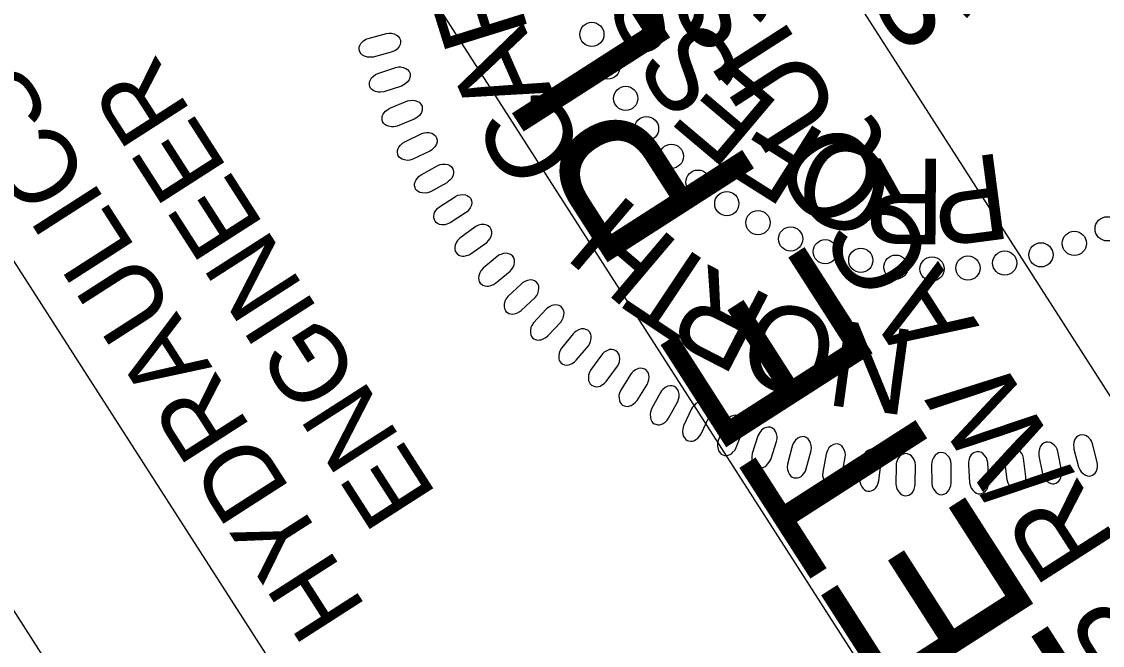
# Model space of a CAD drawing. Extents: x 476646 to 478477, y 498681 to 500689.
# Drawn here: x 476726.9 to 476798.5, y 500059.2 to 500100.5 of the extents above; entities that cross this region are included whole.
import ezdxf

# ---------------------------------------------------------------- set-up
doc = ezdxf.new("R2010")
doc.units = 0
for name, color, linetype in [('Sheet PE Seal Cell', 7, 'Continuous'), ('Sheet Plan CELL', 7, 'Continuous'), ('Sheet Sticker Incomplete CELL', 7, 'Continuous')]:
    doc.layers.add(name, color=color, linetype=linetype)

msp = doc.modelspace()

# ---------------------------------------------------------------- linework, layer by layer
at = {"layer": 'Sheet PE Seal Cell'}
for points in [[(476751.41, 500098.486), (476750.223, 500098.175), (476750.001, 500098.156), (476749.853, 500098.171), (476749.66, 500098.237), (476749.53, 500098.303), (476749.424, 500098.391), (476749.359, 500098.482), (476749.312, 500098.586), (476749.303, 500098.699), (476749.302, 500098.823), (476749.333, 500098.94), (476749.403, 500099.065), (476749.465, 500099.144), (476749.592, 500099.247), (476749.751, 500099.35), (476749.9, 500099.412), (476751.113, 500099.737), (476751.283, 500099.759), (476751.43, 500099.75), (476751.607, 500099.704), (476751.77, 500099.631), (476751.872, 500099.557), (476751.97, 500099.42), (476752.026, 500099.28), (476752.026, 500099.126), (476752.004, 500099.012), (476751.94, 500098.864), (476751.806, 500098.706), (476751.65, 500098.595), (476751.531, 500098.533)], [(476752.101, 500096.256), (476750.937, 500095.872), (476750.717, 500095.839), (476750.567, 500095.845), (476750.371, 500095.898), (476750.237, 500095.955), (476750.126, 500096.037), (476750.055, 500096.124), (476750, 500096.224), (476749.984, 500096.337), (476749.976, 500096.46), (476750, 500096.578), (476750.062, 500096.708), (476750.118, 500096.79), (476750.24, 500096.901), (476750.391, 500097.014), (476750.536, 500097.086), (476751.727, 500097.487), (476751.895, 500097.518), (476752.042, 500097.519), (476752.221, 500097.484), (476752.389, 500097.421), (476752.495, 500097.354), (476752.601, 500097.224), (476752.667, 500097.088), (476752.675, 500096.934), (476752.661, 500096.819), (476752.606, 500096.667), (476752.483, 500096.5), (476752.333, 500096.38), (476752.22, 500096.311)], [(476752.947, 500094.06), (476751.809, 500093.603), (476751.591, 500093.556), (476751.443, 500093.553), (476751.243, 500093.594), (476751.106, 500093.643), (476750.99, 500093.717), (476750.914, 500093.8), (476750.853, 500093.896), (476750.83, 500094.008), (476750.813, 500094.13), (476750.83, 500094.25), (476750.884, 500094.384), (476750.935, 500094.469), (476751.049, 500094.587), (476751.193, 500094.71), (476751.333, 500094.79), (476752.497, 500095.265), (476752.662, 500095.306), (476752.808, 500095.317), (476752.99, 500095.293), (476753.161, 500095.241), (476753.272, 500095.181), (476753.385, 500095.057), (476753.46, 500094.926), (476753.478, 500094.773), (476753.471, 500094.657), (476753.426, 500094.502), (476753.313, 500094.328), (476753.172, 500094.198), (476753.062, 500094.122)], [(476753.969, 500091.936), (476752.862, 500091.409), (476752.647, 500091.348), (476752.499, 500091.336), (476752.298, 500091.364), (476752.157, 500091.405), (476752.037, 500091.472), (476751.956, 500091.549), (476751.89, 500091.641), (476751.86, 500091.752), (476751.835, 500091.872), (476751.844, 500091.992), (476751.889, 500092.13), (476751.935, 500092.218), (476752.041, 500092.344), (476752.178, 500092.474), (476752.312, 500092.563), (476753.444, 500093.11), (476753.607, 500093.162), (476753.751, 500093.182), (476753.934, 500093.17), (476754.109, 500093.129), (476754.222, 500093.075), (476754.344, 500092.959), (476754.426, 500092.833), (476754.454, 500092.681), (476754.455, 500092.565), (476754.419, 500092.407), (476754.318, 500092.226), (476754.184, 500092.088), (476754.08, 500092.005)], [(476755.098, 500089.854), (476754.025, 500089.257), (476753.816, 500089.183), (476753.668, 500089.161), (476753.465, 500089.177), (476753.322, 500089.209), (476753.198, 500089.268), (476753.113, 500089.34), (476753.04, 500089.429), (476753.004, 500089.536), (476752.972, 500089.655), (476752.973, 500089.776), (476753.009, 500089.916), (476753.05, 500090.007), (476753.148, 500090.138), (476753.276, 500090.278), (476753.404, 500090.375), (476754.499, 500090.992), (476754.658, 500091.055), (476754.802, 500091.083), (476754.985, 500091.082), (476755.161, 500091.052), (476755.279, 500091.006), (476755.407, 500090.898), (476755.498, 500090.777), (476755.535, 500090.627), (476755.542, 500090.511), (476755.517, 500090.351), (476755.427, 500090.165), (476755.303, 500090.019), (476755.203, 500089.929)], [(476756.349, 500087.853), (476755.317, 500087.191), (476755.112, 500087.105), (476754.965, 500087.073), (476754.763, 500087.076), (476754.618, 500087.099), (476754.49, 500087.15), (476754.4, 500087.216), (476754.323, 500087.3), (476754.279, 500087.405), (476754.239, 500087.522), (476754.234, 500087.642), (476754.261, 500087.784), (476754.296, 500087.878), (476754.386, 500088.015), (476754.504, 500088.163), (476754.627, 500088.268), (476755.68, 500088.952), (476755.835, 500089.025), (476755.977, 500089.062), (476756.16, 500089.073), (476756.338, 500089.054), (476756.457, 500089.015), (476756.593, 500088.915), (476756.69, 500088.8), (476756.737, 500088.653), (476756.752, 500088.538), (476756.737, 500088.377), (476756.658, 500088.185), (476756.543, 500088.031), (476756.45, 500087.936)], [(476756.959, 500086.92), (476755.97, 500086.194), (476755.815, 500086.034), (476755.734, 500085.91), (476755.663, 500085.718), (476755.632, 500085.575), (476755.634, 500085.438), (476755.664, 500085.33), (476755.714, 500085.227), (476755.797, 500085.149), (476755.891, 500085.07), (476756.001, 500085.021), (476756.144, 500084.996), (476756.243, 500084.995), (476756.404, 500085.029), (476756.584, 500085.087), (476756.726, 500085.163), (476757.744, 500085.901), (476757.867, 500086.019), (476757.953, 500086.138), (476758.029, 500086.304), (476758.075, 500086.478), (476758.082, 500086.603), (476758.037, 500086.765), (476757.965, 500086.897), (476757.844, 500086.994), (476757.742, 500087.049), (476757.586, 500087.092), (476757.379, 500087.089), (476757.194, 500087.036), (476757.072, 500086.984)], [(476758.446, 500084.977), (476757.505, 500084.19), (476757.36, 500084.021), (476757.287, 500083.892), (476757.228, 500083.697), (476757.206, 500083.552), (476757.217, 500083.415), (476757.254, 500083.309), (476757.31, 500083.21), (476757.397, 500083.137), (476757.497, 500083.064), (476757.61, 500083.022), (476757.753, 500083.005), (476757.853, 500083.011), (476758.011, 500083.055), (476758.187, 500083.124), (476758.324, 500083.209), (476759.293, 500084.009), (476759.409, 500084.135), (476759.488, 500084.259), (476759.553, 500084.43), (476759.588, 500084.605), (476759.586, 500084.731), (476759.532, 500084.89), (476759.452, 500085.018), (476759.325, 500085.107), (476759.22, 500085.155), (476759.062, 500085.189), (476758.855, 500085.172), (476758.674, 500085.108), (476758.556, 500085.048)], [(476760.042, 500083.171), (476759.152, 500082.328), (476759.018, 500082.15), (476758.952, 500082.016), (476758.907, 500081.817), (476758.894, 500081.672), (476758.913, 500081.535), (476758.956, 500081.432), (476759.019, 500081.336), (476759.11, 500081.269), (476759.214, 500081.203), (476759.329, 500081.168), (476759.475, 500081.16), (476759.573, 500081.172), (476759.728, 500081.227), (476759.899, 500081.306), (476760.031, 500081.4), (476760.948, 500082.259), (476761.056, 500082.392), (476761.126, 500082.52), (476761.18, 500082.695), (476761.204, 500082.873), (476761.195, 500082.998), (476761.131, 500083.153), (476761.042, 500083.275), (476760.911, 500083.356), (476760.802, 500083.398), (476760.643, 500083.422), (476760.437, 500083.392), (476760.261, 500083.317), (476760.146, 500083.249)], [(476761.684, 500081.486), (476760.848, 500080.588), (476760.726, 500080.402), (476760.669, 500080.264), (476760.636, 500080.063), (476760.633, 500079.917), (476760.66, 500079.782), (476760.709, 500079.681), (476760.778, 500079.59), (476760.874, 500079.528), (476760.982, 500079.469), (476761.099, 500079.442), (476761.244, 500079.444), (476761.342, 500079.461), (476761.493, 500079.525), (476761.659, 500079.615), (476761.784, 500079.717), (476762.645, 500080.632), (476762.745, 500080.771), (476762.807, 500080.904), (476762.85, 500081.082), (476762.863, 500081.261), (476762.846, 500081.385), (476762.772, 500081.536), (476762.676, 500081.652), (476762.54, 500081.725), (476762.429, 500081.76), (476762.268, 500081.773), (476762.065, 500081.731), (476761.893, 500081.645), (476761.784, 500081.571)], [(476763.467, 500079.857), (476762.689, 500078.908), (476762.579, 500078.715), (476762.531, 500078.574), (476762.51, 500078.372), (476762.515, 500078.225), (476762.551, 500078.092), (476762.607, 500077.995), (476762.681, 500077.909), (476762.781, 500077.852), (476762.892, 500077.801), (476763.01, 500077.78), (476763.155, 500077.791), (476763.252, 500077.815), (476763.399, 500077.888), (476763.559, 500077.989), (476763.678, 500078.098), (476764.48, 500079.065), (476764.57, 500079.21), (476764.623, 500079.347), (476764.656, 500079.527), (476764.657, 500079.706), (476764.633, 500079.829), (476764.549, 500079.975), (476764.446, 500080.085), (476764.305, 500080.149), (476764.192, 500080.177), (476764.031, 500080.181), (476763.831, 500080.125), (476763.665, 500080.029), (476763.56, 500079.948)], [(476765.342, 500078.445), (476764.625, 500077.449), (476764.528, 500077.249), (476764.488, 500077.106), (476764.48, 500076.903), (476764.495, 500076.757), (476764.54, 500076.627), (476764.601, 500076.533), (476764.681, 500076.452), (476764.784, 500076.402), (476764.898, 500076.357), (476765.018, 500076.344), (476765.161, 500076.364), (476765.256, 500076.394), (476765.398, 500076.476), (476765.552, 500076.587), (476765.663, 500076.703), (476766.403, 500077.719), (476766.484, 500077.869), (476766.529, 500078.009), (476766.55, 500078.191), (476766.54, 500078.369), (476766.508, 500078.491), (476766.415, 500078.632), (476766.305, 500078.735), (476766.161, 500078.789), (476766.047, 500078.81), (476765.885, 500078.804), (476765.689, 500078.737), (476765.53, 500078.629), (476765.43, 500078.542)], [(476767.271, 500077.167), (476766.618, 500076.128), (476766.533, 500075.923), (476766.503, 500075.776), (476766.507, 500075.573), (476766.532, 500075.429), (476766.584, 500075.301), (476766.651, 500075.212), (476766.736, 500075.135), (476766.841, 500075.093), (476766.958, 500075.054), (476767.079, 500075.049), (476767.221, 500075.078), (476767.314, 500075.114), (476767.45, 500075.205), (476767.597, 500075.325), (476767.7, 500075.448), (476768.374, 500076.508), (476768.446, 500076.664), (476768.482, 500076.806), (476768.491, 500076.989), (476768.471, 500077.167), (476768.431, 500077.285), (476768.33, 500077.42), (476768.214, 500077.516), (476768.066, 500077.562), (476767.951, 500077.575), (476767.79, 500077.559), (476767.599, 500077.479), (476767.446, 500077.363), (476767.352, 500077.269)], [(476769.249, 500075.961), (476768.663, 500074.883), (476768.59, 500074.672), (476768.57, 500074.525), (476768.587, 500074.323), (476768.62, 500074.18), (476768.68, 500074.056), (476768.753, 500073.971), (476768.843, 500073.9), (476768.95, 500073.864), (476769.07, 500073.833), (476769.19, 500073.835), (476769.33, 500073.873), (476769.421, 500073.915), (476769.551, 500074.014), (476769.69, 500074.143), (476769.786, 500074.273), (476770.392, 500075.373), (476770.454, 500075.532), (476770.481, 500075.677), (476770.478, 500075.859), (476770.447, 500076.036), (476770.399, 500076.152), (476770.29, 500076.28), (476770.168, 500076.369), (476770.018, 500076.406), (476769.902, 500076.412), (476769.743, 500076.385), (476769.557, 500076.293), (476769.412, 500076.167), (476769.324, 500076.068)], [(476771.299, 500074.88), (476770.782, 500073.767), (476770.723, 500073.552), (476770.712, 500073.404), (476770.741, 500073.203), (476770.784, 500073.063), (476770.852, 500072.943), (476770.93, 500072.863), (476771.023, 500072.797), (476771.133, 500072.768), (476771.254, 500072.745), (476771.374, 500072.755), (476771.511, 500072.801), (476771.599, 500072.848), (476771.724, 500072.956), (476771.853, 500073.093), (476771.941, 500073.229), (476772.478, 500074.365), (476772.529, 500074.528), (476772.547, 500074.674), (476772.533, 500074.856), (476772.49, 500075.03), (476772.436, 500075.143), (476772.318, 500075.264), (476772.191, 500075.345), (476772.039, 500075.372), (476771.923, 500075.37), (476771.766, 500075.334), (476771.586, 500075.23), (476771.449, 500075.095), (476771.368, 500074.991)], [(476773.52, 500073.927), (476773.073, 500072.785), (476773.028, 500072.567), (476773.026, 500072.418), (476773.069, 500072.218), (476773.12, 500072.081), (476773.195, 500071.966), (476773.278, 500071.891), (476773.375, 500071.832), (476773.487, 500071.809), (476773.609, 500071.794), (476773.728, 500071.811), (476773.862, 500071.866), (476773.947, 500071.919), (476774.064, 500072.034), (476774.185, 500072.179), (476774.264, 500072.319), (476774.728, 500073.487), (476774.769, 500073.654), (476774.778, 500073.8), (476774.753, 500073.981), (476774.699, 500074.152), (476774.638, 500074.262), (476774.513, 500074.374), (476774.381, 500074.447), (476774.227, 500074.465), (476774.112, 500074.456), (476773.957, 500074.41), (476773.784, 500074.295), (476773.656, 500074.152), (476773.581, 500074.042)], [(476775.704, 500073.094), (476775.331, 500071.926), (476775.299, 500071.706), (476775.306, 500071.557), (476775.362, 500071.361), (476775.42, 500071.227), (476775.503, 500071.117), (476775.591, 500071.048), (476775.692, 500070.994), (476775.805, 500070.979), (476775.928, 500070.971), (476776.046, 500070.996), (476776.176, 500071.059), (476776.257, 500071.117), (476776.367, 500071.239), (476776.478, 500071.391), (476776.549, 500071.537), (476776.938, 500072.731), (476776.968, 500072.9), (476776.968, 500073.046), (476776.931, 500073.225), (476776.867, 500073.393), (476776.799, 500073.499), (476776.667, 500073.603), (476776.531, 500073.668), (476776.377, 500073.675), (476776.262, 500073.66), (476776.111, 500073.603), (476775.945, 500073.478), (476775.827, 500073.328), (476775.758, 500073.213)], [(476777.965, 500072.421), (476777.665, 500071.231), (476777.648, 500071.009), (476777.664, 500070.861), (476777.732, 500070.669), (476777.799, 500070.539), (476777.888, 500070.434), (476777.98, 500070.37), (476778.084, 500070.323), (476778.198, 500070.316), (476778.321, 500070.315), (476778.437, 500070.348), (476778.563, 500070.419), (476778.641, 500070.481), (476778.742, 500070.61), (476778.844, 500070.77), (476778.905, 500070.918), (476779.219, 500072.136), (476779.239, 500072.305), (476779.229, 500072.452), (476779.181, 500072.628), (476779.106, 500072.792), (476779.032, 500072.893), (476778.894, 500072.989), (476778.754, 500073.045), (476778.599, 500073.042), (476778.485, 500073.02), (476778.338, 500072.954), (476778.181, 500072.82), (476778.072, 500072.661), (476778.011, 500072.543)], [(476780.217, 500071.891), (476779.993, 500070.685), (476779.989, 500070.462), (476780.015, 500070.315), (476780.094, 500070.128), (476780.17, 500070.002), (476780.266, 500069.903), (476780.361, 500069.845), (476780.468, 500069.805), (476780.581, 500069.804), (476780.705, 500069.812), (476780.818, 500069.851), (476780.94, 500069.93), (476781.013, 500069.998), (476781.107, 500070.132), (476781.198, 500070.298), (476781.25, 500070.451), (476781.487, 500071.685), (476781.495, 500071.855), (476781.477, 500072.001), (476781.418, 500072.175), (476781.333, 500072.332), (476781.252, 500072.428), (476781.109, 500072.516), (476780.966, 500072.563), (476780.811, 500072.551), (476780.7, 500072.521), (476780.556, 500072.446), (476780.407, 500072.301), (476780.308, 500072.137), (476780.256, 500072.016)], [(476794.312, 500071.78), (476794.547, 500070.577), (476794.626, 500070.368), (476794.704, 500070.241), (476794.847, 500070.096), (476794.963, 500070.007), (476795.088, 500069.951), (476795.199, 500069.932), (476795.313, 500069.933), (476795.419, 500069.975), (476795.531, 500070.027), (476795.622, 500070.105), (476795.705, 500070.223), (476795.749, 500070.313), (476795.786, 500070.473), (476795.81, 500070.661), (476795.802, 500070.822), (476795.568, 500072.056), (476795.513, 500072.218), (476795.442, 500072.347), (476795.324, 500072.486), (476795.187, 500072.602), (476795.076, 500072.661), (476794.911, 500072.69), (476794.761, 500072.681), (476794.622, 500072.613), (476794.528, 500072.544), (476794.422, 500072.422), (476794.338, 500072.233), (476794.307, 500072.043), (476794.302, 500071.91)], [(476796.627, 500072.225), (476796.938, 500071.038), (476797.03, 500070.836), (476797.115, 500070.713), (476797.267, 500070.578), (476797.389, 500070.496), (476797.518, 500070.448), (476797.628, 500070.436), (476797.742, 500070.445), (476797.846, 500070.493), (476797.954, 500070.552), (476798.04, 500070.636), (476798.116, 500070.759), (476798.153, 500070.852), (476798.181, 500071.013), (476798.193, 500071.202), (476798.175, 500071.362), (476797.864, 500072.58), (476797.799, 500072.738), (476797.72, 500072.862), (476797.593, 500072.993), (476797.449, 500073.099), (476797.335, 500073.153), (476797.168, 500073.171), (476797.018, 500073.152), (476796.884, 500073.075), (476796.796, 500073.001), (476796.697, 500072.873), (476796.625, 500072.678), (476796.605, 500072.487), (476796.609, 500072.354)], [(476782.592, 500071.497), (476782.444, 500070.28), (476782.455, 500070.058), (476782.489, 500069.913), (476782.58, 500069.731), (476782.663, 500069.61), (476782.765, 500069.518), (476782.864, 500069.466), (476782.973, 500069.432), (476783.087, 500069.438), (476783.209, 500069.454), (476783.32, 500069.5), (476783.436, 500069.587), (476783.505, 500069.659), (476783.59, 500069.799), (476783.672, 500069.97), (476783.713, 500070.126), (476783.872, 500071.372), (476783.87, 500071.543), (476783.842, 500071.687), (476783.773, 500071.856), (476783.678, 500072.008), (476783.591, 500072.099), (476783.443, 500072.178), (476783.297, 500072.215), (476783.144, 500072.194), (476783.034, 500072.157), (476782.895, 500072.074), (476782.757, 500071.92), (476782.668, 500071.75), (476782.623, 500071.624)], [(476784.848, 500071.133), (476784.844, 500069.907), (476784.881, 500069.687), (476784.932, 500069.548), (476785.044, 500069.378), (476785.141, 500069.268), (476785.253, 500069.188), (476785.357, 500069.148), (476785.469, 500069.127), (476785.582, 500069.147), (476785.701, 500069.177), (476785.806, 500069.235), (476785.911, 500069.335), (476785.971, 500069.415), (476786.039, 500069.564), (476786.1, 500069.744), (476786.122, 500069.903), (476786.134, 500071.159), (476786.112, 500071.329), (476786.067, 500071.469), (476785.978, 500071.629), (476785.867, 500071.768), (476785.769, 500071.848), (476785.613, 500071.909), (476785.464, 500071.929), (476785.314, 500071.89), (476785.209, 500071.84), (476785.082, 500071.741), (476784.962, 500071.572), (476784.894, 500071.393), (476784.864, 500071.263)], [(476787.206, 500071.204), (476787.212, 500069.977), (476787.25, 500069.758), (476787.303, 500069.619), (476787.416, 500069.449), (476787.514, 500069.34), (476787.626, 500069.261), (476787.731, 500069.222), (476787.844, 500069.202), (476787.956, 500069.223), (476788.075, 500069.253), (476788.179, 500069.313), (476788.283, 500069.413), (476788.343, 500069.493), (476788.41, 500069.644), (476788.469, 500069.823), (476788.49, 500069.983), (476788.492, 500071.24), (476788.468, 500071.409), (476788.423, 500071.549), (476788.333, 500071.707), (476788.22, 500071.847), (476788.123, 500071.926), (476787.965, 500071.985), (476787.815, 500072.004), (476787.666, 500071.964), (476787.562, 500071.913), (476787.435, 500071.813), (476787.317, 500071.643), (476787.25, 500071.463), (476787.22, 500071.333)], [(476789.635, 500071.213), (476789.718, 500069.989), (476789.77, 500069.773), (476789.831, 500069.637), (476789.955, 500069.475), (476790.059, 500069.372), (476790.176, 500069.3), (476790.283, 500069.268), (476790.396, 500069.255), (476790.507, 500069.283), (476790.624, 500069.321), (476790.725, 500069.387), (476790.822, 500069.494), (476790.876, 500069.577), (476790.934, 500069.731), (476790.981, 500069.914), (476790.993, 500070.076), (476790.915, 500071.329), (476790.882, 500071.497), (476790.827, 500071.633), (476790.727, 500071.786), (476790.606, 500071.918), (476790.504, 500071.991), (476790.343, 500072.041), (476790.192, 500072.05), (476790.046, 500072), (476789.945, 500071.944), (476789.825, 500071.835), (476789.717, 500071.659), (476789.662, 500071.475), (476789.641, 500071.343)], [(476792.021, 500071.427), (476792.181, 500070.21), (476792.246, 500069.998), (476792.316, 500069.866), (476792.449, 500069.712), (476792.56, 500069.616), (476792.681, 500069.552), (476792.79, 500069.526), (476792.904, 500069.521), (476793.013, 500069.555), (476793.128, 500069.6), (476793.223, 500069.673), (476793.314, 500069.785), (476793.363, 500069.872), (476793.41, 500070.029), (476793.446, 500070.215), (476793.449, 500070.376), (476793.292, 500071.624), (476793.248, 500071.788), (476793.185, 500071.921), (476793.076, 500072.068), (476792.946, 500072.191), (476792.84, 500072.258), (476792.676, 500072.297), (476792.525, 500072.297), (476792.382, 500072.238), (476792.285, 500072.175), (476792.172, 500072.06), (476792.075, 500071.876), (476792.032, 500071.69), (476792.019, 500071.557)]]:
    msp.add_lwpolyline(points, close=True, dxfattribs=at)
for centre in [(476764.707, 500099.672), (476765.762, 500097.511), (476766.951, 500095.435), (476768.328, 500093.434), (476769.974, 500091.604), (476771.733, 500089.894), (476773.641, 500088.469), (476775.708, 500087.211), (476798.825, 500086.803), (476777.865, 500086.135), (476796.653, 500085.836), (476780.159, 500085.288), (476782.513, 500084.716), (476794.441, 500085.08), (476784.836, 500084.266), (476787.231, 500084.147), (476789.608, 500084.204), (476792.044, 500084.537)]:
    msp.add_circle(centre, 0.801, dxfattribs=at)
at = {"layer": 'Sheet Plan CELL'}
msp.add_line((476803.67, 499941.179), (476695.634, 500109.534), dxfattribs=at)
msp.add_line((476803.67, 499941.179), (476695.634, 500109.534), dxfattribs=at)
msp.add_lwpolyline([(476760.156, 500032.132), (476706.155, 500116.283), (476800.848, 500177.047), (476854.856, 500092.886)], close=True, dxfattribs=at)
at = {"layer": 'Sheet Sticker Incomplete CELL'}
msp.add_lwpolyline([(476847.189, 500000.642), (476827.409, 499987.953), (476748.033, 500111.68), (476767.813, 500124.369)], close=True, dxfattribs=at)

# ---------------------------------------------------------------- texts
at = {"layer": 'Sheet PE Seal Cell'}
for s, height, rotation, p in [('SEAL', 6.2363, 122.66317, (476791.003, 500101.233)), ('R', 5.669, 107.29078, (476760.585, 500099.786)), ('S', 5.669, 116.03105, (476772.818, 500099.957)), ('A', 5.669, 113.78013, (476762.187, 500095.817)), ('S', 5.669, 123.97084, (476774.988, 500096.762)), ('E', 5.669, 139.85044, (476777.29, 500094.951)), ('C', 5.669, 120.26949, (476764.483, 500091.853)), ('F', 5.669, 147.79024, (476780.416, 500092.928)), ('O', 5.669, 163.66983, (476785.054, 500091.511)), ('R', 5.669, 179.54943, (476788.122, 500091.443)), ('P', 5.669, 187.48922, (476791.863, 500091.839)), ('H', 5.669, 139.73756, (476770.66, 500085.712)), ('T', 5.669, 146.22692, (476773.564, 500083.797)), ('R', 5.669, 152.71627, (476776.918, 500082.122)), ('O', 5.669, 165.69499, (476781.343, 500080.832)), ('N', 5.669, 172.18434, (476786.311, 500080.043))]:
    msp.add_text(s, height=height, rotation=rotation, dxfattribs=at).set_placement(p)
at = {"layer": 'Sheet Plan CELL'}
for s, p in [('ENGINEER', (476754.501, 500069.167)), ('HYDRAULICS', (476749.83, 500061.7))]:
    msp.add_text(s, height=5.0001, rotation=122.68182, dxfattribs=at).set_placement(p)
at = {"layer": 'Sheet Sticker Incomplete CELL'}
for s, height, p in [('INCOMPLETE PLANS', 11.52, (476832.508, 500001.857)), ('DO NOT USE FOR R/W ACQUISITION', 5.76, (476836.603, 500008.346))]:
    msp.add_text(s, height=height, rotation=122.68181, dxfattribs=at).set_placement(p)

doc.saveas('drawing.dxf')
